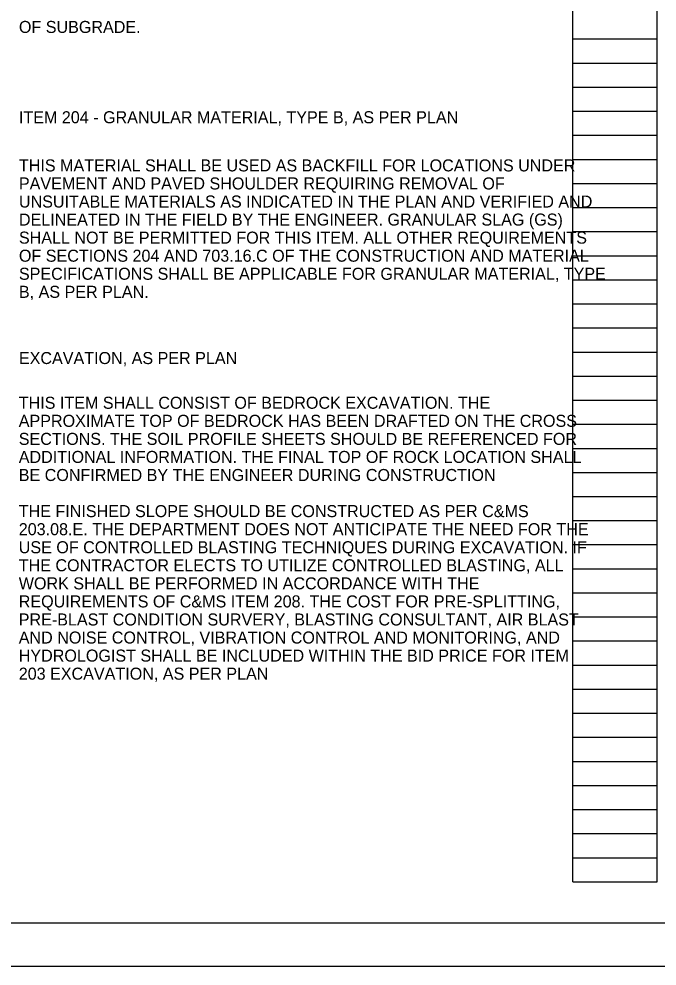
# Model space of a CAD drawing. Extents: x 0 to 34, y 0 to 22.
# Drawn here: x 17.24 to 24.66, y 0 to 11.01 of the extents above; entities that cross this region are included whole.
import ezdxf

# ---------------------------------------------------------------- set-up
doc = ezdxf.new("R2010")
doc.units = 0
for name, color, linetype in [('SH_Border', 7, 'Continuous'), ('SH_Cut_Line', 7, 'Continuous'), ('SH_Data', 7, 'Continuous'), ('SH_Text', 7, 'Continuous')]:
    doc.layers.add(name, color=color, linetype=linetype)

msp = doc.modelspace()

# ---------------------------------------------------------------- linework, layer by layer
at = {"layer": 'SH_Border'}
msp.add_lwpolyline([(1.5, 21.5), (33.5, 21.5), (33.5, 0.5), (1.5, 0.5)], close=True, dxfattribs=at)
at = {"layer": 'SH_Cut_Line'}
msp.add_lwpolyline([(0, 0), (34, 0), (34, 22), (0, 22)], close=True, dxfattribs=at)
at = {"layer": 'SH_Data'}
for p, q in [((23.68, 0.98), (23.68, 21.14)), ((24.66, 0.98), (24.66, 21.14)), ((23.68, 10.78), (24.66, 10.78)), ((23.68, 10.5), (24.66, 10.5)), ((23.68, 10.22), (24.66, 10.22)), ((23.68, 9.94), (24.66, 9.94)), ((23.68, 9.66), (24.66, 9.66)), ((23.68, 9.38), (24.66, 9.38)), ((23.68, 9.1), (24.66, 9.1)), ((23.68, 8.82), (24.66, 8.82)), ((23.68, 8.54), (24.66, 8.54)), ((23.68, 8.26), (24.66, 8.26)), ((23.68, 7.98), (24.66, 7.98)), ((23.68, 7.7), (24.66, 7.7)), ((23.68, 7.42), (24.66, 7.42)), ((23.68, 7.14), (24.66, 7.14)), ((23.68, 6.86), (24.66, 6.86)), ((23.68, 6.58), (24.66, 6.58)), ((23.68, 6.3), (24.66, 6.3)), ((23.68, 6.02), (24.66, 6.02)), ((23.68, 5.74), (24.66, 5.74)), ((23.68, 5.46), (24.66, 5.46)), ((23.68, 5.18), (24.66, 5.18)), ((23.68, 4.9), (24.66, 4.9)), ((23.68, 4.62), (24.66, 4.62)), ((23.68, 4.34), (24.66, 4.34)), ((23.68, 4.06), (24.66, 4.06)), ((23.68, 3.78), (24.66, 3.78)), ((23.68, 3.5), (24.66, 3.5)), ((23.68, 3.22), (24.66, 3.22)), ((23.68, 2.94), (24.66, 2.94)), ((23.68, 2.66), (24.66, 2.66)), ((23.68, 2.38), (24.66, 2.38)), ((23.68, 2.1), (24.66, 2.1)), ((23.68, 1.82), (24.66, 1.82)), ((23.68, 1.54), (24.66, 1.54)), ((23.68, 1.26), (24.66, 1.26)), ((23.68, 0.98), (24.66, 0.98))]:
    msp.add_line(p, q, dxfattribs=at)

# ---------------------------------------------------------------- texts
at = {"layer": 'SH_Text'}
for s, p in [('OF SUBGRADE.', (17.24, 10.85)), ('ITEM 204 - GRANULAR MATERIAL, TYPE B, AS PER PLAN', (17.24, 9.8)), ('THIS MATERIAL SHALL BE USED AS BACKFILL FOR LOCATIONS UNDER ', (17.24, 9.24)), ('PAVEMENT AND PAVED SHOULDER REQUIRING REMOVAL OF ', (17.24, 9.03)), ('UNSUITABLE MATERIALS AS INDICATED IN THE PLAN AND VERIFIED AND ', (17.24, 8.82)), ('DELINEATED IN THE FIELD BY THE ENGINEER. GRANULAR SLAG (GS) ', (17.24, 8.61)), ('SHALL NOT BE PERMITTED FOR THIS ITEM. ALL OTHER REQUIREMENTS ', (17.24, 8.4)), ('OF SECTIONS 204 AND 703.16.C OF THE CONSTRUCTION AND MATERIAL ', (17.24, 8.19)), ('SPECIFICATIONS SHALL BE APPLICABLE FOR GRANULAR MATERIAL, TYPE ', (17.24, 7.98)), ('B, AS PER PLAN.', (17.24, 7.77)), ('EXCAVATION, AS PER PLAN ', (17.24, 7)), ('THIS ITEM SHALL CONSIST OF BEDROCK EXCAVATION. THE ', (17.238, 6.48)), ('APPROXIMATE TOP OF BEDROCK HAS BEEN DRAFTED ON THE CROSS ', (17.238, 6.27)), ('SECTIONS. THE SOIL PROFILE SHEETS SHOULD BE REFERENCED FOR ', (17.238, 6.06)), ('ADDITIONAL INFORMATION. THE FINAL TOP OF ROCK LOCATION SHALL ', (17.238, 5.85)), ('BE CONFIRMED BY THE ENGINEER DURING CONSTRUCTION', (17.238, 5.64)), ('THE FINISHED SLOPE SHOULD BE CONSTRUCTED AS PER C&MS ', (17.238, 5.22)), ('203.08.E. THE DEPARTMENT DOES NOT ANTICIPATE THE NEED FOR THE ', (17.238, 5.01)), ('USE OF CONTROLLED BLASTING TECHNIQUES DURING EXCAVATION. IF ', (17.238, 4.8)), ('THE CONTRACTOR ELECTS TO UTILIZE CONTROLLED BLASTING, ALL ', (17.238, 4.59)), ('WORK SHALL BE PERFORMED IN ACCORDANCE WITH THE ', (17.238, 4.38)), ('REQUIREMENTS OF C&MS ITEM 208. THE COST FOR PRE-SPLITTING, ', (17.238, 4.17)), ('PRE-BLAST CONDITION SURVERY, BLASTING CONSULTANT, AIR BLAST ', (17.238, 3.96)), ('AND NOISE CONTROL, VIBRATION CONTROL AND MONITORING, AND ', (17.238, 3.75)), ('HYDROLOGIST SHALL BE INCLUDED WITHIN THE BID PRICE FOR ITEM ', (17.238, 3.54)), ('203 EXCAVATION, AS PER PLAN ', (17.238, 3.33))]:
    msp.add_text(s, height=0.14, dxfattribs=at).set_placement(p)

doc.saveas('drawing.dxf')
